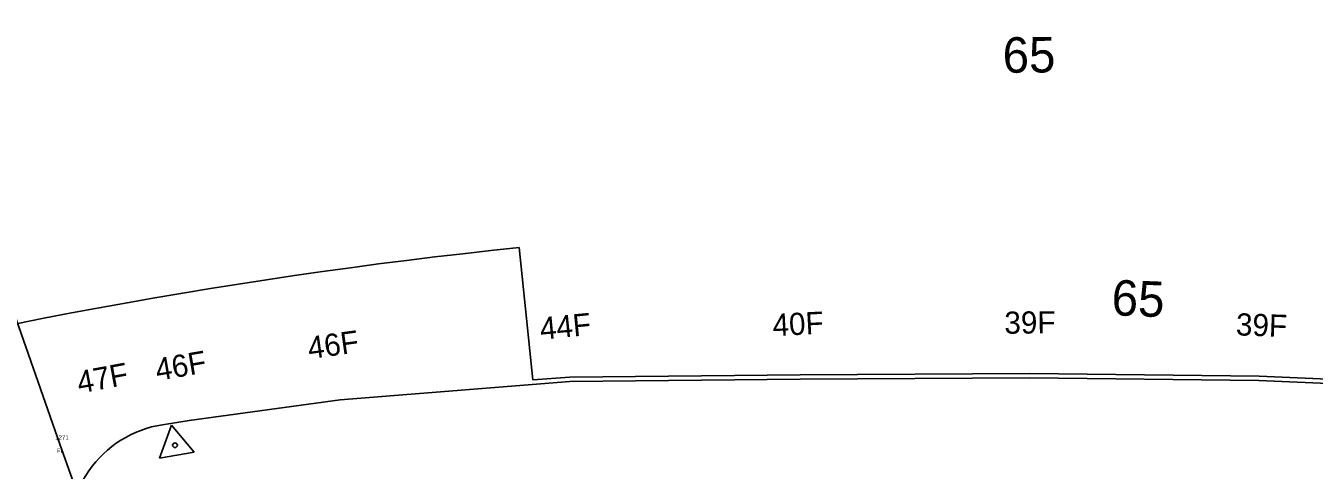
# Model space of a CAD drawing. Extents: x 1964982 to 1970452, y 1116335 to 1119906.
# Drawn here: x 1967933.9 to 1968224.5, y 1118001.8 to 1118101.9 of the extents above; entities that cross this region are included whole.
import ezdxf

# ---------------------------------------------------------------- set-up
doc = ezdxf.new("R2010")
doc.units = 0
for name, color, linetype in [('RD_EX_Fence_Other', 7, 'Continuous'), ('RD_EX_Fence_Other_txCode', 7, 'Continuous'), ('RD_HC_Data_Rel', 7, 'Continuous'), ('RD_HC_TX_Rel_Sta50', 7, 'Continuous'), ('RD_HC_TX_Sta50', 7, 'Continuous'), ('RD_PD_CstnLmt', 7, 'Continuous'), ('RD_PD_RW', 7, 'Continuous'), ('RD_PD_TX_CstnLmt', 7, 'Continuous'), ('RD_SMD_Locator', 7, 'Continuous')]:
    doc.layers.add(name, color=color, linetype=linetype)

msp = doc.modelspace()

# ---------------------------------------------------------------- linework, layer by layer
at = {"layer": 'RD_EX_Fence_Other'}
msp.add_lwpolyline([(1967920.92, 1118368.66), (1967937.87, 1118342.4), (1967954.81, 1118301.31), (1967965.67, 1118250.56), (1967963.61, 1118188.09), (1967935.71, 1118144.56), (1967926.43, 1118106.38), (1967926.25, 1118051.25), (1967941.61, 1118007.63), (1967945.93, 1117995.37)], dxfattribs=at)
at = {"layer": 'RD_HC_Data_Rel'}
for p, q in [((1967964.05, 1118004.45), (1967966.79, 1118011.91)), ((1967966.79, 1118011.91), (1967971.88, 1118005.81)), ((1967964.05, 1118004.45), (1967971.88, 1118005.81))]:
    msp.add_line(p, q, dxfattribs=at)
msp.add_circle((1967967.57, 1118007.39), 0.529, dxfattribs=at)
at = {"layer": 'RD_PD_CstnLmt'}
for p, q in [((1968004.82, 1118017.66), (1968056.65, 1118021.76)), ((1968056.65, 1118021.76), (1968108.59, 1118022.27)), ((1968108.59, 1118022.27), (1968160.34, 1118022.56)), ((1968160.34, 1118022.56), (1968212.04, 1118021.98)), ((1968212.04, 1118021.98), (1968263.71, 1118019.64)), ((1967970.8, 1118012.98), (1968004.82, 1118017.66)), ((1967964.73, 1118012.02), (1967970.8, 1118012.98))]:
    msp.add_line(p, q, dxfattribs=at)
msp.add_arc((1967968.63, 1117987.33), 25, 98.9687, 191.2007, dxfattribs=at)
at = {"layer": 'RD_PD_RW'}
for p, q in [((1968048.26, 1118022.1), (1968045.17, 1118051.94)), ((1968056.6, 1118022.76), (1968108.58, 1118023.27)), ((1968108.58, 1118023.27), (1968160.34, 1118023.56)), ((1968160.34, 1118023.56), (1968212.07, 1118022.98)), ((1968048.26, 1118022.1), (1968056.6, 1118022.76)), ((1968212.07, 1118022.98), (1968263.78, 1118020.64))]:
    msp.add_line(p, q, dxfattribs=at)
msp.add_arc((1968170.83, 1116837.51), 1220.92, 95.90724, 115.04633, dxfattribs=at)
at = {"layer": 'RD_SMD_Locator'}
msp.add_circle((1967941.61, 1118007.63), 0.001, dxfattribs=at)

# ---------------------------------------------------------------- texts
at = {"layer": 'RD_EX_Fence_Other_txCode'}
for s, p in [('1271', (1967940.54, 1118008.63)), ('FL', (1967940.88, 1118005.63))]:
    msp.add_text(s, height=1, dxfattribs=at).set_placement(p)
at = {"layer": 'RD_HC_TX_Rel_Sta50'}
msp.add_text('65', height=8, rotation=0.5072, dxfattribs=at).set_placement((1968154.26, 1118091.33))
at = {"layer": 'RD_HC_TX_Sta50'}
msp.add_text('65', height=8, rotation=357.7266, dxfattribs=at).set_placement((1968178.7, 1118036.71))
at = {"layer": 'RD_PD_TX_CstnLmt'}
for s, rotation, p in [('44F', 5.5072, (1968050.1, 1118031.17)), ('40F', 3.0072, (1968102.46, 1118031.96)), ('39F', 0.5072, (1968154.64, 1118032.51)), ('39F', 358.0072, (1968206.78, 1118032.17)), ('46F', 8.0072, (1967997.87, 1118026.79)), ('46F', 9.6572, (1967963.59, 1118021.9)), ('47F', 10.5072, (1967945.98, 1118019.03))]:
    msp.add_text(s, height=5, rotation=rotation, dxfattribs=at).set_placement(p)

doc.saveas('drawing.dxf')
